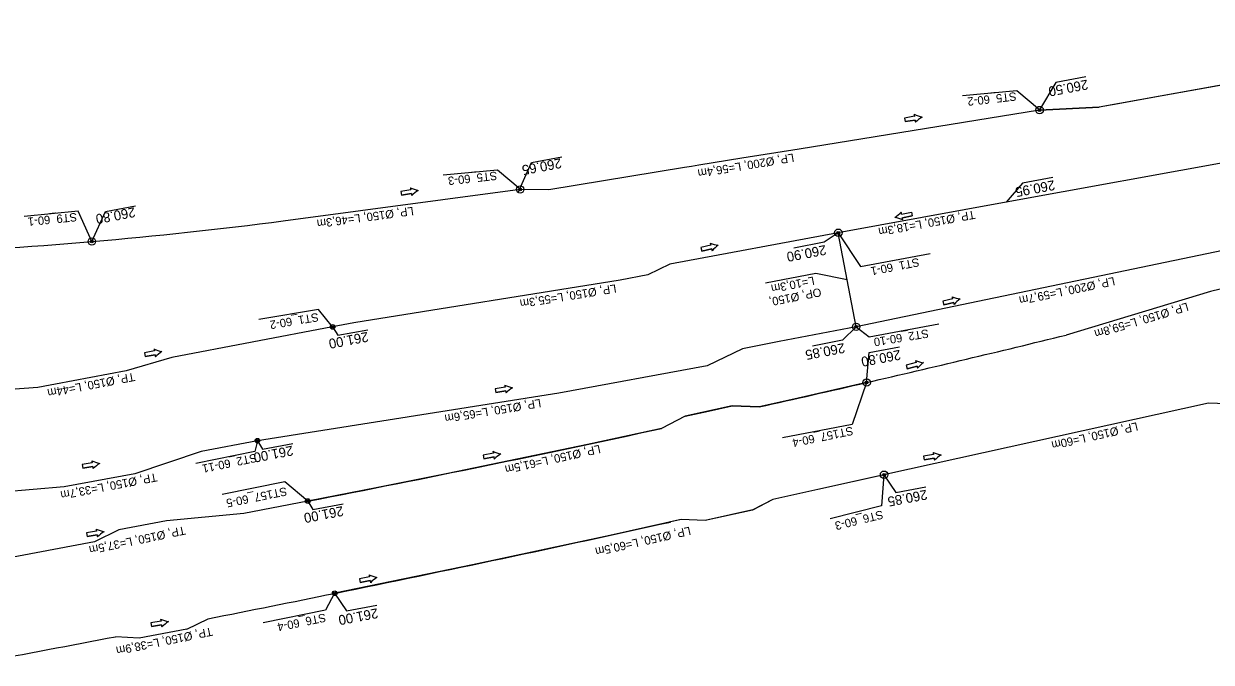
# Model space of a CAD drawing. Extents: x -1 to 65640748, y -22 to 5530284.
# Drawn here: x 6558248.4 to 6558375.8, y 5528803.4 to 5528872 of the extents above; entities that cross this region are included whole.
import ezdxf

# ---------------------------------------------------------------- set-up
doc = ezdxf.new("R2010")
doc.units = 0
for name, color, linetype in [('TOR_PROF-studnie i osadniki', 7, 'Continuous'), ('TOR_PS_ODW-drenaze', 7, 'Continuous'), ('TOR_PS_ODW-drenokolektory', 7, 'Continuous'), ('TOR_PS_ODW-kolektory', 7, 'Continuous'), ('TOR_PS_ODW-studnie PEHD', 7, 'Continuous'), ('TOR_PS_OPIS_O-opisy rurociagow', 7, 'Continuous'), ('TOR_PS_OPIS_O-opisy studni', 7, 'Continuous'), ('TOR_PS_OPIS_T-INFO', 7, 'Continuous')]:
    doc.layers.add(name, color=color, linetype=linetype)

msp = doc.modelspace()

# ---------------------------------------------------------------- linework, layer by layer
at = {"layer": 'TOR_PROF-studnie i osadniki'}
for centre, radius in [((6558281.52, 5528839.41), 0.25), ((6558281.52, 5528839.41), 0.125), ((6558273.45, 5528827.2), 0.25), ((6558273.45, 5528827.2), 0.125), ((6558278.85, 5528820.71), 0.25), ((6558278.85, 5528820.71), 0.125), ((6558281.74, 5528810.81), 0.25), ((6558281.74, 5528810.81), 0.125)]:
    msp.add_circle(centre, radius, dxfattribs=at)
at = {"layer": 'TOR_PS_ODW-drenaze'}
for p, q in [((6558413.09, 5528863.56), (6558353.79, 5528852.8)), ((6558353.79, 5528852.8), (6558335.79, 5528849.53)), ((6558265.88, 5528806.97), (6558268.15, 5528808.08)), ((6558265.88, 5528806.97), (6558260.77, 5528805.98)), ((6558260.77, 5528805.98), (6558258.24, 5528806.15))]:
    msp.add_line(p, q, dxfattribs=at)
for points in [[(6558281.52, 5528839.41), (6558264.25, 5528836.14), (6558259.37, 5528834.71), (6558249.89, 5528832.92), (6558245.46, 5528832.58), (6558238.34, 5528831.23)], [(6558337.7, 5528839.42), (6558329.43, 5528837.84), (6558325.49, 5528837.08), (6558321.7, 5528835.25), (6558305.78, 5528832.3), (6558273.45, 5528827.2)], [(6558338.83, 5528833.44), (6558331, 5528831.65), (6558327.28, 5528830.82), (6558324.41, 5528830.94), (6558319.34, 5528829.82), (6558316.8, 5528828.5), (6558308.88, 5528826.8), (6558293.87, 5528823.68), (6558286.37, 5528822.18), (6558278.85, 5528820.71)], [(6558273.45, 5528827.2), (6558267.4, 5528826.05), (6558260.3, 5528823.63), (6558252.72, 5528822.24), (6558242.7, 5528821.37), (6558240.44, 5528820.94)], [(6558340.7, 5528823.54), (6558333.58, 5528821.96), (6558328.76, 5528820.89), (6558326.62, 5528819.77), (6558321.5, 5528818.62), (6558318.94, 5528818.72), (6558311.26, 5528817.03), (6558296.52, 5528813.87), (6558281.74, 5528810.81)], [(6558278.85, 5528820.7), (6558271.98, 5528819.39), (6558263.68, 5528818.58), (6558258.57, 5528817.61), (6558255.96, 5528816.35), (6558242.09, 5528813.72)]]:
    msp.add_lwpolyline(points, dxfattribs=at)
for centre, radius, start, end in [((6557953.1, 5530501.63), 1712.2, 280.96732, 282.2639), ((6557841.99, 5530969.37), 2202.9, 281.51447, 282.47333), ((6557841.99, 5530969.37), 2202.9, 281.15423, 281.51447), ((6557841.99, 5530969.37), 2202.9, 280.50651, 280.89165)]:
    msp.add_arc(centre, radius, start, end, dxfattribs=at)
at = {"layer": 'TOR_PS_ODW-drenokolektory'}
for p, q in [((6558397.37, 5528869.05), (6558363.77, 5528863.02)), ((6558357.39, 5528862.7), (6558363.77, 5528863.02)), ((6558301.65, 5528854.18), (6558276.22, 5528850.79)), ((6558315.03, 5528833.98), (6558315.03, 5528833.98)), ((6558321.87, 5528830.38), (6558324.41, 5528830.94)), ((6558324.41, 5528830.94), (6558327.28, 5528830.82)), ((6558319.34, 5528829.82), (6558316.8, 5528828.5)), ((6558319.34, 5528829.82), (6558321.87, 5528830.38))]:
    msp.add_line(p, q, dxfattribs=at)
for points in [[(6558409, 5528871.97), (6558402.64, 5528870.81), (6558400.18, 5528870.38), (6558398.85, 5528869.75), (6558397.75, 5528869.24), (6558397.37, 5528869.05), (6558396.39, 5528868.88), (6558383.56, 5528866.57), (6558370.56, 5528864.24), (6558367.39, 5528863.67), (6558365.81, 5528863.39), (6558363.77, 5528863.02), (6558357.39, 5528862.7), (6558331.59, 5528858.51), (6558325.43, 5528857.52), (6558322.36, 5528857.02), (6558320.82, 5528856.77), (6558320.05, 5528856.64), (6558319.28, 5528856.52), (6558304.71, 5528854.14), (6558301.65, 5528854.18)], [(6558396.31, 5528850.81), (6558380.2, 5528848.21), (6558377.05, 5528847.61), (6558337.7, 5528839.42)], [(6558335.79, 5528849.53), (6558317.72, 5528846.17), (6558315.34, 5528845.01), (6558312.37, 5528844.44), (6558283.79, 5528839.84), (6558281.52, 5528839.41)], [(6558396.93, 5528847.52), (6558378.86, 5528843.97), (6558375.75, 5528843.21), (6558360.24, 5528838.54)], [(6558399.02, 5528836.44), (6558383.46, 5528832.99), (6558381.03, 5528831.71), (6558378.44, 5528831.12), (6558375.51, 5528831.23), (6558340.67, 5528823.53)], [(6558340.67, 5528823.53), (6558328.76, 5528820.89), (6558326.58, 5528819.75), (6558321.5, 5528818.62), (6558318.94, 5528818.72), (6558317.79, 5528818.47)]]:
    msp.add_lwpolyline(points, dxfattribs=at)
for centre, radius, start, end in [((6558212.95, 5529343.95), 497.2, 274.9294, 277.3112), ((6558212.95, 5529343.95), 497.2, 272.5475, 274.9294), ((6557953.1, 5530501.63), 1712.2, 283.01941, 283.75581), ((6557953.1, 5530501.63), 1712.2, 282.62313, 283.01941)]:
    msp.add_arc(centre, radius, start, end, dxfattribs=at)
at = {"layer": 'TOR_PS_ODW-kolektory'}
msp.add_line((6558337.7, 5528839.42), (6558335.79, 5528849.53), dxfattribs=at)
at = {"layer": 'TOR_PS_ODW-studnie PEHD'}
for centre, radius in [((6558357.39, 5528862.7), 0.4), ((6558357.39, 5528862.7), 0.145), ((6558301.65, 5528854.18), 0.4), ((6558301.65, 5528854.18), 0.145), ((6558335.79, 5528849.53), 0.4), ((6558335.79, 5528849.53), 0.145), ((6558255.68, 5528848.59), 0.4), ((6558255.68, 5528848.59), 0.145), ((6558281.52, 5528839.41), 0.25), ((6558281.52, 5528839.41), 0.112), ((6558337.7, 5528839.42), 0.4), ((6558337.7, 5528839.42), 0.145), ((6558338.83, 5528833.44), 0.4), ((6558338.83, 5528833.44), 0.145), ((6558273.45, 5528827.2), 0.25), ((6558273.45, 5528827.2), 0.112), ((6558340.7, 5528823.54), 0.4), ((6558340.7, 5528823.54), 0.145), ((6558278.85, 5528820.71), 0.25), ((6558278.85, 5528820.71), 0.112), ((6558281.74, 5528810.81), 0.25), ((6558281.74, 5528810.81), 0.112)]:
    msp.add_circle(centre, radius, dxfattribs=at)
at = {"layer": 'TOR_PS_OPIS_O-opisy rurociagow'}
for p, q in [((6558343.98, 5528862.03), (6558342.9, 5528861.85)), ((6558343.98, 5528862.03), (6558342.9, 5528861.85)), ((6558342.9, 5528861.85), (6558342.97, 5528861.46)), ((6558342.9, 5528861.85), (6558342.97, 5528861.46)), ((6558342.97, 5528861.46), (6558344.05, 5528861.63)), ((6558344.05, 5528861.63), (6558342.97, 5528861.46)), ((6558289.91, 5528854.15), (6558288.83, 5528853.97)), ((6558289.91, 5528854.15), (6558288.83, 5528853.97)), ((6558288.83, 5528853.97), (6558288.9, 5528853.58)), ((6558288.83, 5528853.97), (6558288.9, 5528853.58)), ((6558288.9, 5528853.58), (6558289.98, 5528853.75)), ((6558289.98, 5528853.75), (6558288.9, 5528853.58)), ((6558342.58, 5528851.51), (6558343.65, 5528851.73)), ((6558342.58, 5528851.51), (6558343.65, 5528851.73)), ((6558343.73, 5528851.34), (6558342.66, 5528851.12)), ((6558342.66, 5528851.12), (6558343.73, 5528851.34)), ((6558343.65, 5528851.73), (6558343.73, 5528851.34)), ((6558343.65, 5528851.73), (6558343.73, 5528851.34)), ((6558322.11, 5528848.2), (6558321.05, 5528847.94)), ((6558322.11, 5528848.2), (6558321.05, 5528847.94)), ((6558321.05, 5528847.94), (6558321.14, 5528847.55)), ((6558321.05, 5528847.94), (6558321.14, 5528847.55)), ((6558321.14, 5528847.55), (6558322.2, 5528847.81)), ((6558322.2, 5528847.81), (6558321.14, 5528847.55)), ((6558348.07, 5528842.44), (6558347.01, 5528842.17)), ((6558348.07, 5528842.44), (6558347.01, 5528842.17)), ((6558347.01, 5528842.17), (6558347.1, 5528841.79)), ((6558347.01, 5528842.17), (6558347.1, 5528841.79)), ((6558347.1, 5528841.79), (6558348.17, 5528842.05)), ((6558348.17, 5528842.05), (6558347.1, 5528841.79)), ((6558262.41, 5528836.83), (6558261.33, 5528836.64)), ((6558262.41, 5528836.83), (6558261.33, 5528836.64)), ((6558261.33, 5528836.64), (6558261.4, 5528836.24)), ((6558261.33, 5528836.64), (6558261.4, 5528836.24)), ((6558261.4, 5528836.24), (6558262.48, 5528836.43)), ((6558262.48, 5528836.43), (6558261.4, 5528836.24)), ((6558344.14, 5528835.58), (6558343.08, 5528835.32)), ((6558344.14, 5528835.58), (6558343.08, 5528835.32)), ((6558343.08, 5528835.32), (6558343.18, 5528834.93)), ((6558343.08, 5528835.32), (6558343.18, 5528834.93)), ((6558343.18, 5528834.93), (6558344.24, 5528835.19)), ((6558344.24, 5528835.19), (6558343.18, 5528834.93)), ((6558300.03, 5528832.95), (6558298.96, 5528832.76)), ((6558300.03, 5528832.95), (6558298.96, 5528832.76)), ((6558298.96, 5528832.76), (6558299.03, 5528832.36)), ((6558298.96, 5528832.76), (6558299.03, 5528832.36)), ((6558299.03, 5528832.36), (6558300.1, 5528832.56)), ((6558300.1, 5528832.56), (6558299.03, 5528832.36)), ((6558298.77, 5528825.85), (6558297.69, 5528825.66)), ((6558298.77, 5528825.85), (6558297.69, 5528825.66)), ((6558297.69, 5528825.66), (6558297.76, 5528825.26)), ((6558297.69, 5528825.66), (6558297.76, 5528825.26)), ((6558297.76, 5528825.26), (6558298.84, 5528825.45)), ((6558298.84, 5528825.45), (6558297.76, 5528825.26)), ((6558346.02, 5528825.73), (6558344.94, 5528825.53)), ((6558346.02, 5528825.73), (6558344.94, 5528825.53)), ((6558344.94, 5528825.53), (6558345.01, 5528825.14)), ((6558344.94, 5528825.53), (6558345.01, 5528825.14)), ((6558345.01, 5528825.14), (6558346.09, 5528825.33)), ((6558346.09, 5528825.33), (6558345.01, 5528825.14)), ((6558255.72, 5528824.83), (6558254.65, 5528824.64)), ((6558255.72, 5528824.83), (6558254.65, 5528824.64)), ((6558254.65, 5528824.64), (6558254.72, 5528824.24)), ((6558254.65, 5528824.64), (6558254.72, 5528824.24)), ((6558254.72, 5528824.24), (6558255.79, 5528824.43)), ((6558255.79, 5528824.43), (6558254.72, 5528824.24)), ((6558256.19, 5528817.48), (6558255.12, 5528817.29)), ((6558256.19, 5528817.48), (6558255.12, 5528817.29)), ((6558255.12, 5528817.29), (6558255.19, 5528816.9)), ((6558255.12, 5528817.29), (6558255.19, 5528816.9)), ((6558255.19, 5528816.9), (6558256.26, 5528817.09)), ((6558256.26, 5528817.09), (6558255.19, 5528816.9)), ((6558285.47, 5528812.57), (6558284.4, 5528812.38)), ((6558285.47, 5528812.57), (6558284.4, 5528812.38)), ((6558284.4, 5528812.38), (6558284.47, 5528811.98)), ((6558284.4, 5528812.38), (6558284.47, 5528811.98)), ((6558284.47, 5528811.98), (6558285.54, 5528812.18)), ((6558285.54, 5528812.18), (6558284.47, 5528811.98)), ((6558263.1, 5528807.83), (6558262.02, 5528807.63)), ((6558263.1, 5528807.83), (6558262.02, 5528807.63)), ((6558262.02, 5528807.63), (6558262.09, 5528807.24)), ((6558262.02, 5528807.63), (6558262.09, 5528807.24)), ((6558262.09, 5528807.24), (6558263.17, 5528807.43)), ((6558263.17, 5528807.43), (6558262.09, 5528807.24))]:
    msp.add_line(p, q, dxfattribs=at)
for points in [[(6558343.94, 5528862.25), (6558343.94, 5528862.25)], [(6558344.07, 5528861.41), (6558344.07, 5528861.41)], [(6558289.87, 5528854.37), (6558289.87, 5528854.37)], [(6558290, 5528853.53), (6558290, 5528853.53)], [(6558342.54, 5528851.73), (6558342.54, 5528851.73)], [(6558342.71, 5528850.9), (6558342.71, 5528850.9)], [(6558322.04, 5528848.42), (6558322.04, 5528848.42)], [(6558322.25, 5528847.59), (6558322.25, 5528847.59)], [(6558348.01, 5528842.65), (6558348.01, 5528842.65)], [(6558348.21, 5528841.83), (6558348.21, 5528841.83)], [(6558262.36, 5528837.05), (6558262.36, 5528837.05)], [(6558262.51, 5528836.21), (6558262.51, 5528836.21)], [(6558344.08, 5528835.8), (6558344.08, 5528835.8)], [(6558344.28, 5528834.97), (6558344.28, 5528834.97)], [(6558299.98, 5528833.17), (6558299.98, 5528833.17)], [(6558300.13, 5528832.33), (6558300.13, 5528832.33)], [(6558298.72, 5528826.07), (6558298.72, 5528826.07)], [(6558345.97, 5528825.95), (6558345.97, 5528825.95)], [(6558255.67, 5528825.05), (6558255.67, 5528825.05)], [(6558255.82, 5528824.21), (6558255.82, 5528824.21)], [(6558298.87, 5528825.23), (6558298.87, 5528825.23)], [(6558346.11, 5528825.11), (6558346.11, 5528825.11)], [(6558256.14, 5528817.7), (6558256.14, 5528817.7)], [(6558256.29, 5528816.86), (6558256.29, 5528816.86)], [(6558285.42, 5528812.79), (6558285.42, 5528812.79)], [(6558285.57, 5528811.95), (6558285.57, 5528811.95)], [(6558263.05, 5528808.05), (6558263.05, 5528808.05)], [(6558263.2, 5528807.21), (6558263.2, 5528807.21)]]:
    msp.add_lwpolyline(points, dxfattribs=at)
for centre, radius, start, end in [((6558345.98, 5528866.72), 4.92, 245.4514, 255.8332), ((6558344.39, 5528862.23), 0.458, 177.566, 206.0272), ((6558345.98, 5528866.72), 4.92, 245.4514, 255.8332), ((6558344.39, 5528862.23), 0.458, 177.566, 206.0272), ((6558344.5, 5528861.57), 0.458, 172.2953, 200.7566), ((6558344.5, 5528861.57), 0.458, 172.2953, 200.7566), ((6558347.42, 5528857.8), 4.92, 122.4893, 132.8711), ((6558347.42, 5528857.8), 4.92, 122.4893, 132.8711), ((6558291.91, 5528858.84), 4.92, 245.4514, 255.8332), ((6558290.32, 5528854.35), 0.458, 177.566, 206.0272), ((6558291.91, 5528858.84), 4.92, 245.4514, 255.8332), ((6558290.32, 5528854.35), 0.458, 177.566, 206.0272), ((6558290.43, 5528853.69), 0.458, 172.2953, 200.7566), ((6558290.43, 5528853.69), 0.458, 172.2953, 200.7566), ((6558293.35, 5528849.92), 4.92, 122.4893, 132.8711), ((6558293.35, 5528849.92), 4.92, 122.4893, 132.8711), ((6558339.06, 5528855.21), 4.92, 304.7037, 315.0855), ((6558339.06, 5528855.21), 4.92, 304.7037, 315.0855), ((6558340.84, 5528846.35), 4.92, 67.6658, 78.0476), ((6558340.84, 5528846.35), 4.92, 67.6658, 78.0476), ((6558342.12, 5528851.56), 0.458, 354.5097, 22.9709), ((6558342.12, 5528851.56), 0.458, 354.5097, 22.9709), ((6558342.25, 5528850.9), 0.458, 359.7803, 28.2416), ((6558342.25, 5528850.9), 0.458, 359.7803, 28.2416), ((6558323.71, 5528853.04), 4.92, 250.1356, 260.5175), ((6558322.5, 5528848.44), 0.458, 182.2502, 210.7114), ((6558323.71, 5528853.04), 4.92, 250.1356, 260.5175), ((6558322.5, 5528848.44), 0.458, 182.2502, 210.7114), ((6558322.66, 5528847.79), 0.458, 176.9795, 205.4408), ((6558322.66, 5528847.79), 0.458, 176.9795, 205.4408), ((6558325.88, 5528844.27), 4.92, 127.1735, 137.5554), ((6558325.88, 5528844.27), 4.92, 127.1735, 137.5554), ((6558349.68, 5528847.28), 4.92, 250.1356, 260.5175), ((6558348.46, 5528842.67), 0.458, 182.2502, 210.7114), ((6558349.68, 5528847.28), 4.92, 250.1356, 260.5175), ((6558348.46, 5528842.67), 0.458, 182.2502, 210.7114), ((6558348.62, 5528842.02), 0.458, 176.9795, 205.4408), ((6558348.62, 5528842.02), 0.458, 176.9795, 205.4408), ((6558351.84, 5528838.51), 4.92, 127.1735, 137.5554), ((6558351.84, 5528838.51), 4.92, 127.1735, 137.5554), ((6558264.33, 5528841.55), 4.92, 246.381, 256.7628), ((6558262.82, 5528837.04), 0.458, 178.4955, 206.9568), ((6558264.33, 5528841.55), 4.92, 246.381, 256.7628), ((6558262.82, 5528837.04), 0.458, 178.4955, 206.9568), ((6558262.93, 5528836.38), 0.458, 173.2249, 201.6861), ((6558262.93, 5528836.38), 0.458, 173.2249, 201.6861), ((6558265.91, 5528832.66), 4.92, 123.4189, 133.8007), ((6558265.91, 5528832.66), 4.92, 123.4189, 133.8007), ((6558345.75, 5528840.42), 4.92, 250.1356, 260.5175), ((6558344.54, 5528835.82), 0.458, 182.2502, 210.7114), ((6558345.75, 5528840.42), 4.92, 250.1356, 260.5175), ((6558344.54, 5528835.82), 0.458, 182.2502, 210.7114), ((6558347.91, 5528831.66), 4.92, 127.1735, 137.5554), ((6558347.91, 5528831.66), 4.92, 127.1735, 137.5554), ((6558344.7, 5528835.17), 0.458, 176.9795, 205.4408), ((6558344.7, 5528835.17), 0.458, 176.9795, 205.4408), ((6558301.95, 5528837.68), 4.92, 246.381, 256.7628), ((6558300.44, 5528833.16), 0.458, 178.4955, 206.9568), ((6558301.95, 5528837.68), 4.92, 246.381, 256.7628), ((6558300.44, 5528833.16), 0.458, 178.4955, 206.9568), ((6558300.56, 5528832.5), 0.458, 173.2249, 201.6861), ((6558300.56, 5528832.5), 0.458, 173.2249, 201.6861), ((6558303.54, 5528828.78), 4.92, 123.4189, 133.8007), ((6558303.54, 5528828.78), 4.92, 123.4189, 133.8007), ((6558300.69, 5528830.57), 4.92, 246.381, 256.7628), ((6558299.18, 5528826.06), 0.458, 178.4955, 206.9568), ((6558300.69, 5528830.57), 4.92, 246.381, 256.7628), ((6558299.18, 5528826.06), 0.458, 178.4955, 206.9568), ((6558299.29, 5528825.4), 0.458, 173.2249, 201.6861), ((6558299.29, 5528825.4), 0.458, 173.2249, 201.6861), ((6558302.27, 5528821.68), 4.92, 123.4189, 133.8007), ((6558302.27, 5528821.68), 4.92, 123.4189, 133.8007), ((6558347.94, 5528830.45), 4.92, 246.381, 256.7628), ((6558346.42, 5528825.93), 0.458, 178.4955, 206.9568), ((6558347.94, 5528830.45), 4.92, 246.381, 256.7628), ((6558346.42, 5528825.93), 0.458, 178.4955, 206.9568), ((6558346.54, 5528825.28), 0.458, 173.2249, 201.6861), ((6558346.54, 5528825.28), 0.458, 173.2249, 201.6861), ((6558349.52, 5528821.56), 4.92, 123.4189, 133.8007), ((6558349.52, 5528821.56), 4.92, 123.4189, 133.8007), ((6558257.64, 5528829.55), 4.92, 246.381, 256.7628), ((6558256.13, 5528825.03), 0.458, 178.4955, 206.9568), ((6558257.64, 5528829.55), 4.92, 246.381, 256.7628), ((6558256.13, 5528825.03), 0.458, 178.4955, 206.9568), ((6558256.25, 5528824.38), 0.458, 173.2249, 201.6861), ((6558256.25, 5528824.38), 0.458, 173.2249, 201.6861), ((6558259.23, 5528820.66), 4.92, 123.4189, 133.8007), ((6558259.23, 5528820.66), 4.92, 123.4189, 133.8007), ((6558258.11, 5528822.21), 4.92, 246.381, 256.7628), ((6558256.6, 5528817.69), 0.458, 178.4955, 206.9568), ((6558258.11, 5528822.21), 4.92, 246.381, 256.7628), ((6558256.6, 5528817.69), 0.458, 178.4955, 206.9568), ((6558256.72, 5528817.03), 0.458, 173.2249, 201.6861), ((6558256.72, 5528817.03), 0.458, 173.2249, 201.6861), ((6558259.69, 5528813.32), 4.92, 123.4189, 133.8007), ((6558259.69, 5528813.32), 4.92, 123.4189, 133.8007), ((6558287.39, 5528817.3), 4.92, 246.381, 256.7628), ((6558285.88, 5528812.78), 0.458, 178.4955, 206.9568), ((6558287.39, 5528817.3), 4.92, 246.381, 256.7628), ((6558285.88, 5528812.78), 0.458, 178.4955, 206.9568), ((6558286, 5528812.12), 0.458, 173.2249, 201.6861), ((6558286, 5528812.12), 0.458, 173.2249, 201.6861), ((6558288.98, 5528808.4), 4.92, 123.4189, 133.8007), ((6558288.98, 5528808.4), 4.92, 123.4189, 133.8007), ((6558265.02, 5528812.55), 4.92, 246.381, 256.7628), ((6558263.51, 5528808.03), 0.458, 178.4955, 206.9568), ((6558265.02, 5528812.55), 4.92, 246.381, 256.7628), ((6558263.51, 5528808.03), 0.458, 178.4955, 206.9568), ((6558266.6, 5528803.66), 4.92, 123.4189, 133.8007), ((6558266.6, 5528803.66), 4.92, 123.4189, 133.8007), ((6558263.62, 5528807.38), 0.458, 173.2249, 201.6861), ((6558263.62, 5528807.38), 0.458, 173.2249, 201.6861)]:
    msp.add_arc(centre, radius, start, end, dxfattribs=at)
at = {"layer": 'TOR_PS_OPIS_T-INFO'}
for points in [[(6558362.35, 5528866.28), (6558362.35, 5528866.28), (6558359.12, 5528865.65), (6558357.37, 5528862.72)], [(6558357.37, 5528862.72), (6558354.94, 5528864.78), (6558349.11, 5528864.24)], [(6558301.42, 5528853.85), (6558302.87, 5528857.08), (6558306.11, 5528857.68)], [(6558301.63, 5528854.2), (6558299.2, 5528856.25), (6558293.38, 5528855.71)], [(6558358.8, 5528855.47), (6558358.8, 5528855.47), (6558355.56, 5528854.85), (6558353.79, 5528852.8)], [(6558255.68, 5528848.59), (6558257.13, 5528851.82), (6558260.37, 5528852.42)], [(6558255.68, 5528848.59), (6558254.22, 5528851.83), (6558248.4, 5528851.29)], [(6558335.79, 5528849.53), (6558334.26, 5528848.51), (6558331.02, 5528847.89)], [(6558335.79, 5528849.53), (6558338.17, 5528845.92), (6558345.63, 5528847.31)], [(6558336.75, 5528844.48), (6558333.38, 5528845.15), (6558327.99, 5528844.11)], [(6558281.52, 5528839.41), (6558279.99, 5528841.27), (6558273.61, 5528840.21)], [(6558281.52, 5528839.41), (6558282.08, 5528838.52), (6558285.31, 5528839.12)], [(6558337.7, 5528839.42), (6558336.25, 5528837.98), (6558333.02, 5528837.36)], [(6558337.7, 5528839.42), (6558339.1, 5528838.36), (6558346.56, 5528839.75)], [(6558338.83, 5528833.44), (6558339.11, 5528836.66), (6558342.35, 5528837.26)], [(6558338.83, 5528833.44), (6558337.28, 5528828.94), (6558329.79, 5528827.49)], [(6558273.45, 5528827.2), (6558273.18, 5528826.03), (6558266.84, 5528824.74)], [(6558273.45, 5528827.2), (6558274, 5528826.3), (6558277.24, 5528826.9)], [(6558278.85, 5528820.71), (6558276.38, 5528822.79), (6558269.67, 5528821.42)], [(6558340.67, 5528823.53), (6558340.42, 5528820.22), (6558334.9, 5528818.8)], [(6558340.66, 5528823.53), (6558341.95, 5528821.64), (6558345.19, 5528822.24)], [(6558278.85, 5528820.71), (6558279.4, 5528819.81), (6558282.64, 5528820.41)], [(6558281.73, 5528810.81), (6558280.76, 5528808.99), (6558274.05, 5528807.63)], [(6558281.72, 5528810.81), (6558283.02, 5528808.91), (6558286.25, 5528809.52)]]:
    msp.add_lwpolyline(points, dxfattribs=at)

# ---------------------------------------------------------------- texts
at = {"layer": 'TOR_PS_OPIS_O-opisy rurociagow'}
for s, rotation, p in [('LP, Ø200, L=56,4m', 189.5286, (6558330.96, 5528858.05)), ('LP, Ø150, L=46,3m', 187.6762, (6558290.15, 5528852.32)), ('TP, Ø150, L=18,3m', 190.3486, (6558350.39, 5528851.93)), ('L=10,3m', 191.0982, (6558333.13, 5528844.84)), ('LP, Ø200, L=59,7m', 191.7183, (6558365.37, 5528844.79)), ('LP, Ø150, L=55,3m', 189.1542, (6558311.89, 5528844)), ('OP, Ø150, ', 191.0982, (6558333.87, 5528843.61)), ('LP, Ø150, L=59,8m', 196.635, (6558373.21, 5528842.05)), ('TP, Ø150, L=44m', 190.8086, (6558260.2, 5528834.51)), ('LP, Ø150, L=65,6m', 189.3405, (6558303.81, 5528831.69)), ('LP, Ø150, L=60m', 192.7238, (6558367.83, 5528829.19)), ('LP, Ø150, L=61,5m', 192.5095, (6558310.16, 5528826.77)), ('TP, Ø150, L=33,7m', 190.8086, (6558262.59, 5528823.73)), ('TP, Ø150, L=37,5m', 191.7881, (6558265.62, 5528818.02)), ('LP, Ø150, L=60,5m', 192.7238, (6558319.84, 5528817.98)), ('TP, Ø150, L=38,9m', 191.5656, (6558268.53, 5528807.16))]:
    msp.add_text(s, height=0.9, rotation=rotation, dxfattribs=at).set_placement(p)
at = {"layer": 'TOR_PS_OPIS_O-opisy studni'}
for s, rotation, p in [('ST5_60-2', 186.3657, (6558354.86, 5528864.63)), ('ST5_60-3', 186.3657, (6558299.12, 5528856.11)), ('ST9_60-1', 185.7476, (6558254.03, 5528851.67)), ('ST1_60-1', 191.0514, (6558344.39, 5528846.83)), ('ST1_60-2', 189.567, (6558279.93, 5528840.93)), ('ST2_60-10', 189.419, (6558345.41, 5528839.18)), ('ST157_60-4', 191.652, (6558337.28, 5528828.72)), ('ST2_60-11', 191.811, (6558273.28, 5528825.82)), ('ST157_60-5', 191.4546, (6558276.52, 5528822.22)), ('ST6_60-3', 193.9242, (6558340.48, 5528819.73)), ('ST6_60-4', 191.6429, (6558280.69, 5528808.66))]:
    msp.add_text(s, height=0.9, rotation=rotation, dxfattribs=at).set_placement(p)
at = {"layer": 'TOR_PS_OPIS_T-INFO'}
for s, rotation, p in [('260.50', 190.7159, (6558362.49, 5528865.98)), ('260.65', 190.7506, (6558305.98, 5528857.54)), ('260.95', 190.7159, (6558358.93, 5528855.18)), ('260.80', 190.7506, (6558260.24, 5528852.28)), ('260.90', 190.7159, (6558334.39, 5528848.22)), ('261.00', 190.7506, (6558285.25, 5528838.89)), ('260.85', 190.7159, (6558336.39, 5528837.69)), ('260.80', 190.7506, (6558342.39, 5528836.96)), ('261.00', 190.7506, (6558277.18, 5528826.67)), ('260.85', 190.7506, (6558345.23, 5528821.94)), ('261.00', 190.7506, (6558282.58, 5528820.18)), ('261.00', 190.7506, (6558286.29, 5528809.21))]:
    msp.add_text(s, height=1.05, rotation=rotation, dxfattribs=at).set_placement(p)

doc.saveas('drawing.dxf')
